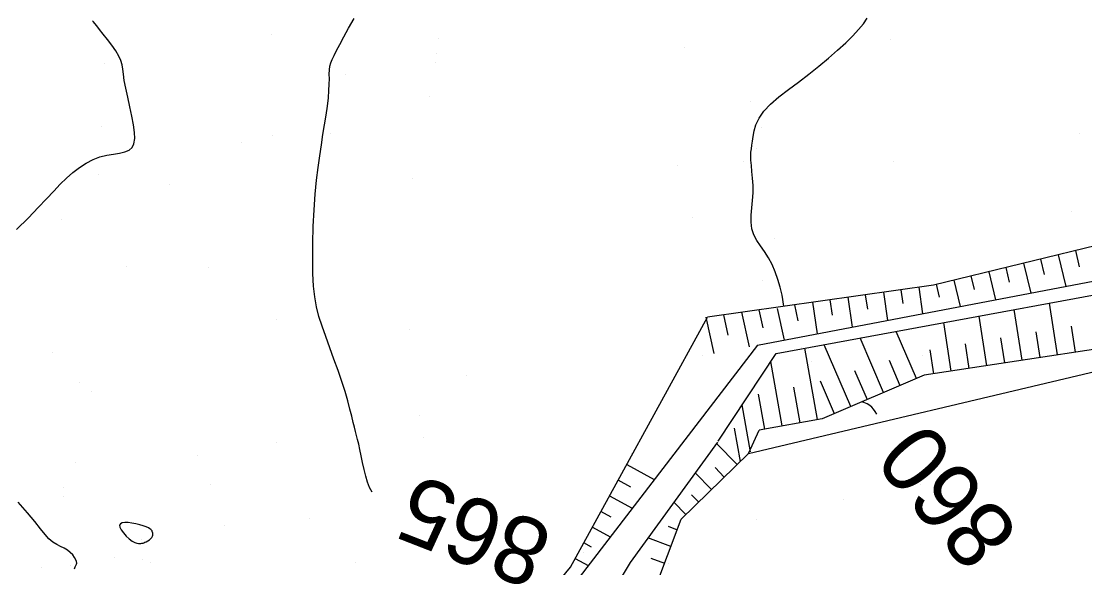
# Model space of a CAD drawing. Extents: x 400243 to 403697, y 4403637 to 4408083.
# Drawn here: x 402707.4 to 402826.2, y 4406153.3 to 4406214.4 of the extents above; entities that cross this region are included whole.
import ezdxf

# ---------------------------------------------------------------- set-up
doc = ezdxf.new("R2010")
doc.units = 0
doc.layers.add('HH_IC', color=7, linetype='Continuous')

msp = doc.modelspace()

# ---------------------------------------------------------------- linework, layer by layer
at = {"layer": 'HH_IC'}
for p, q in [((402735.33, 4406212.94), (402735.33, 4406212.94)), ((402753.96, 4406212.48), (402753.96, 4406212.48)), ((402781.49, 4406211.44), (402781.49, 4406211.44)), ((402804.51, 4406212.31), (402804.51, 4406212.31)), ((402753.8, 4406210.8), (402753.8, 4406210.8)), ((402716.69, 4406209.7), (402716.69, 4406209.7)), ((402753.64, 4406209.76), (402753.64, 4406209.76)), ((402743.57, 4406208.48), (402743.57, 4406208.48)), ((402752.98, 4406205.95), (402752.98, 4406205.95)), ((402788.87, 4406205.46), (402788.87, 4406205.46)), ((402716.39, 4406202.6), (402716.39, 4406202.6)), ((402741.88, 4406201.87), (402741.88, 4406201.87)), ((402790.13, 4406202.49), (402790.13, 4406202.49)), ((402825.61, 4406201.81), (402825.61, 4406201.81)), ((402732.02, 4406200.87), (402732.02, 4406200.87)), ((402735.48, 4406201.64), (402735.48, 4406201.64)), ((402789.54, 4406200.15), (402789.54, 4406200.15)), ((402780.67, 4406198.23), (402780.67, 4406198.23)), ((402788.06, 4406198.68), (402788.06, 4406198.68)), ((402804.78, 4406198.74), (402804.78, 4406198.74)), ((402715.98, 4406197.22), (402715.98, 4406197.22)), ((402723.95, 4406196.14), (402723.95, 4406196.14)), ((402751.05, 4406196.84), (402751.05, 4406196.84)), ((402850.92, 4406195), (402809.29, 4406184.89)), ((402711.84, 4406192.21), (402711.84, 4406192.21)), ((402782.4, 4406192.47), (402782.4, 4406192.47)), ((402824.71, 4406193.08), (402824.71, 4406193.08)), ((402789.65, 4406178.16), (402852.37, 4406190.15)), ((402791.52, 4406190.07), (402791.52, 4406190.07)), ((402825.63, 4406186.94), (402825.19, 4406188.75)), ((402791.71, 4406177.24), (402852.3, 4406188.43)), ((402821.72, 4406186.09), (402821.3, 4406187.81)), ((402823.24, 4406188.28), (402824.1, 4406184.75)), ((402719.14, 4406187.02), (402719.14, 4406187.02)), ((402728.28, 4406186.84), (402728.28, 4406186.84)), ((402815.47, 4406186.39), (402816.23, 4406183.24)), ((402817.81, 4406185.24), (402817.41, 4406186.86)), ((402819.35, 4406187.34), (402820.17, 4406184)), ((402790.23, 4406185.46), (402790.23, 4406185.46)), ((402811.58, 4406185.45), (402812.3, 4406182.49)), ((402813.89, 4406184.39), (402813.52, 4406185.92)), ((402809.29, 4406184.89), (402784.06, 4406181.32)), ((402803.7, 4406184.1), (402804.15, 4406180.94)), ((402805.9, 4406182.85), (402805.68, 4406184.38)), ((402807.66, 4406184.66), (402808.09, 4406181.69)), ((402809.29, 4406184.89), (402809.29, 4406184.89)), ((402809.98, 4406183.55), (402809.64, 4406184.98)), ((402794.2, 4406180.9), (402793.8, 4406182.69)), ((402793.91, 4406182.71), (402793.91, 4406182.71)), ((402795.78, 4406182.98), (402796.29, 4406179.43)), ((402798.01, 4406181.53), (402797.76, 4406183.26)), ((402799.74, 4406183.54), (402800.22, 4406180.18)), ((402801.95, 4406182.19), (402801.72, 4406183.82)), ((402823.15, 4406177.09), (402822.27, 4406182.88)), ((402786.36, 4406179.29), (402785.86, 4406181.57)), ((402787.84, 4406181.85), (402788.69, 4406177.98)), ((402790.28, 4406180.1), (402789.83, 4406182.13)), ((402791.85, 4406182.26), (402792.62, 4406178.73)), ((402819.2, 4406176.49), (402818.33, 4406182.16)), ((402735.85, 4406181.09), (402735.85, 4406181.09)), ((402768.75, 4406153.35), (402784.06, 4406181.32)), ((402783.87, 4406181.29), (402784.76, 4406177.23)), ((402788.65, 4406166.07), (402853.59, 4406181.46)), ((402811.29, 4406175.28), (402810.46, 4406180.7)), ((402815.25, 4406175.88), (402814.4, 4406181.43)), ((402824.68, 4406180.32), (402825.13, 4406177.4)), ((402750.77, 4406179.98), (402750.77, 4406179.98)), ((402807.4, 4406174.45), (402805.15, 4406179.72)), ((402820.74, 4406179.66), (402821.18, 4406176.79)), ((402789.65, 4406178.16), (402761.87, 4406142.01)), ((402794.54, 4406177.97), (402794.54, 4406177.97)), ((402800.05, 4406171.31), (402797.08, 4406178.23)), ((402803.72, 4406172.88), (402801.12, 4406178.98)), ((402829.98, 4406178.14), (402808.25, 4406174.81)), ((402829.98, 4406178.14), (402808.25, 4406174.81)), ((402812.85, 4406178.32), (402813.27, 4406175.58)), ((402816.79, 4406178.99), (402817.22, 4406176.19)), ((402710.9, 4406177.31), (402710.9, 4406177.31)), ((402783.46, 4406176.98), (402783.46, 4406176.98)), ((402785.23, 4406167.46), (402791.71, 4406177.24)), ((402791.71, 4406177.24), (402791.71, 4406177.24)), ((402796.33, 4406169.85), (402794.91, 4406177.83)), ((402808.12, 4406176.98), (402808.12, 4406176.98)), ((402808.91, 4406177.66), (402809.32, 4406174.98)), ((402792.4, 4406169.14), (402791.11, 4406176.34)), ((402795.7, 4406176.3), (402795.7, 4406176.3)), ((402804.35, 4406176.51), (402805.56, 4406173.67)), ((402757.15, 4406174.8), (402757.15, 4406174.8)), ((402780.25, 4406174.35), (402780.25, 4406174.35)), ((402808.25, 4406174.81), (402796.85, 4406169.94)), ((402808.25, 4406174.81), (402796.85, 4406169.94)), ((402800.49, 4406175.35), (402801.88, 4406172.09)), ((402808.25, 4406174.81), (402808.25, 4406174.81)), ((402713.91, 4406173.99), (402713.91, 4406173.99)), ((402793.65, 4406173.48), (402794.37, 4406169.5)), ((402796.64, 4406174.19), (402798.21, 4406170.52)), ((402715.23, 4406172.95), (402715.23, 4406172.95)), ((402785.05, 4406172.19), (402785.05, 4406172.19)), ((402789.73, 4406172.68), (402790.43, 4406168.79)), ((402788.85, 4406166.26), (402787.91, 4406171.51)), ((402751.86, 4406170.36), (402751.86, 4406170.36)), ((402796.85, 4406169.94), (402789.83, 4406168.68)), ((402796.85, 4406169.94), (402789.83, 4406168.68)), ((402796.85, 4406169.94), (402796.85, 4406169.94)), ((402787.04, 4406168.91), (402787.71, 4406165.16)), ((402788.65, 4406166.07), (402789.83, 4406168.68)), ((402735.88, 4406167.29), (402735.88, 4406167.29)), ((402752.32, 4406167.9), (402752.32, 4406167.9)), ((402785.18, 4406167.34), (402775.4, 4406153.87)), ((402785.23, 4406167.46), (402785.23, 4406167.46)), ((402781.12, 4406158.73), (402788.65, 4406166.07)), ((402781.15, 4406167.1), (402781.15, 4406167.1)), ((402787.37, 4406164.82), (402785.07, 4406167.18)), ((402788.65, 4406166.07), (402788.65, 4406166.07)), ((402713.47, 4406165.11), (402713.47, 4406165.11)), ((402727.05, 4406165.88), (402727.05, 4406165.88)), ((402775.52, 4406166.02), (402775.52, 4406166.02)), ((402775.04, 4406164.83), (402778.11, 4406163.15)), ((402784.5, 4406162.03), (402782.68, 4406163.9)), ((402784.9, 4406164.48), (402785.93, 4406163.43)), ((402728.49, 4406162.58), (402728.49, 4406162.58)), ((402775.48, 4406162.31), (402774.08, 4406163.08)), ((402807.89, 4406162.55), (402807.89, 4406162.55)), ((402712.07, 4406161.3), (402712.07, 4406161.3)), ((402712.12, 4406162.27), (402712.12, 4406162.27)), ((402754.69, 4406162.41), (402754.69, 4406162.41)), ((402773.11, 4406161.32), (402775.65, 4406159.94)), ((402782.28, 4406161.45), (402783.07, 4406160.63)), ((402781.64, 4406159.24), (402780.3, 4406160.61)), ((402799.24, 4406160.87), (402799.24, 4406160.87)), ((402773.28, 4406158.95), (402772.15, 4406159.57)), ((402730.08, 4406157.98), (402730.08, 4406157.98)), ((402739.62, 4406158.82), (402739.62, 4406158.82)), ((402760.84, 4406158.02), (402760.84, 4406158.02)), ((402771.19, 4406157.81), (402773.18, 4406156.73)), ((402775.64, 4406144.18), (402781.12, 4406158.73)), ((402779.65, 4406157.92), (402780.67, 4406157.54)), ((402781.12, 4406158.73), (402781.12, 4406158.73)), ((402789.57, 4406158.66), (402789.57, 4406158.66)), ((402779.96, 4406155.67), (402777.4, 4406156.63)), ((402720.84, 4406156.43), (402720.84, 4406156.43)), ((402752.94, 4406156), (402752.94, 4406156)), ((402771.09, 4406155.59), (402770.23, 4406156.06)), ((402717.84, 4406154.39), (402717.84, 4406154.39)), ((402720.93, 4406154.24), (402720.93, 4406154.24)), ((402769.27, 4406154.31), (402770.71, 4406153.52)), ((402770.25, 4406155.04), (402770.25, 4406155.04)), ((402777.72, 4406154.37), (402779.26, 4406153.8)), ((402709.61, 4406153.32), (402709.61, 4406153.32)), ((402712.93, 4406153.58), (402712.93, 4406153.58)), ((402721.85, 4406153.9), (402721.85, 4406153.9)), ((402744.67, 4406153.9), (402744.67, 4406153.9)), ((402775.4, 4406153.87), (402757.34, 4406124.13)), ((402757.7, 4406140), (402768.75, 4406153.35)), ((402768.75, 4406153.35), (402768.75, 4406153.35)), ((402779.68, 4406153.77), (402779.68, 4406153.77))]:
    msp.add_line(p, q, dxfattribs=at)
for points in [[(402706.85, 4406191.13), (402708.17, 4406192.43), (402709.27, 4406193.57), (402710.2, 4406194.55), (402711, 4406195.41), (402711.72, 4406196.17), (402712.42, 4406196.85), (402713.14, 4406197.48), (402713.87, 4406198.04), (402714.63, 4406198.53), (402715.4, 4406198.94), (402716.17, 4406199.23), (402716.94, 4406199.43), (402717.68, 4406199.55), (402718.36, 4406199.65), (402718.95, 4406199.78), (402719.43, 4406199.97), (402719.76, 4406200.28), (402719.96, 4406200.71), (402720.05, 4406201.27), (402720.03, 4406201.96), (402719.92, 4406202.8), (402719.74, 4406203.78), (402719.52, 4406204.84), (402719.28, 4406205.9), (402719.06, 4406206.91), (402718.89, 4406207.79), (402718.79, 4406208.49), (402718.72, 4406209.05), (402718.65, 4406209.54), (402718.52, 4406210), (402718.29, 4406210.5), (402717.94, 4406211.09), (402717.49, 4406211.73), (402717.01, 4406212.37), (402716.53, 4406212.97), (402716.12, 4406213.48), (402715.81, 4406213.87), (402715.59, 4406214.15), (402715.44, 4406214.33), (402715.35, 4406214.45)], [(402746.57, 4406161.72), (402746.28, 4406162.25), (402746.06, 4406162.86), (402745.87, 4406163.54), (402745.69, 4406164.27), (402745.52, 4406165.04), (402745.37, 4406165.79), (402745.22, 4406166.5), (402745.08, 4406167.12), (402744.96, 4406167.64), (402744.85, 4406168.09), (402744.73, 4406168.52), (402744.61, 4406168.99), (402744.46, 4406169.54), (402744.3, 4406170.22), (402744.09, 4406171.03), (402743.85, 4406171.96), (402743.55, 4406173), (402743.2, 4406174.13), (402742.78, 4406175.35), (402742.31, 4406176.61), (402741.84, 4406177.88), (402741.39, 4406179.13), (402740.98, 4406180.31), (402740.64, 4406181.4), (402740.38, 4406182.47), (402740.18, 4406183.57), (402740.04, 4406184.79), (402739.96, 4406186.18), (402739.94, 4406187.8), (402739.95, 4406189.59), (402740.01, 4406191.45), (402740.11, 4406193.3), (402740.23, 4406195.05), (402740.38, 4406196.63), (402740.54, 4406198.06), (402740.72, 4406199.36), (402740.91, 4406200.57), (402741.09, 4406201.72), (402741.27, 4406202.83), (402741.43, 4406203.9), (402741.58, 4406204.9), (402741.69, 4406205.82), (402741.76, 4406206.64), (402741.79, 4406207.36), (402741.8, 4406207.97), (402741.79, 4406208.5), (402741.81, 4406208.97), (402741.85, 4406209.38), (402741.95, 4406209.75), (402742.1, 4406210.14), (402742.32, 4406210.57), (402742.61, 4406211.11), (402742.98, 4406211.79), (402743.42, 4406212.64), (402743.95, 4406213.63), (402744.59, 4406214.71)], [(402792.57, 4406182.52), (402792.38, 4406183.78), (402792.18, 4406184.65), (402791.92, 4406185.52), (402791.61, 4406186.37), (402791.26, 4406187.19), (402790.86, 4406187.95), (402790.42, 4406188.64), (402789.98, 4406189.28), (402789.58, 4406189.89), (402789.24, 4406190.52), (402789.02, 4406191.19), (402788.92, 4406191.92), (402788.93, 4406192.7), (402789, 4406193.52), (402789.08, 4406194.37), (402789.14, 4406195.22), (402789.14, 4406196.05), (402789.09, 4406196.85), (402789.02, 4406197.6), (402788.95, 4406198.28), (402788.9, 4406198.86), (402788.88, 4406199.34), (402788.9, 4406199.75), (402788.95, 4406200.14), (402789.01, 4406200.53), (402789.08, 4406200.99), (402789.15, 4406201.53), (402789.26, 4406202.15), (402789.47, 4406202.83), (402789.81, 4406203.57), (402790.35, 4406204.34), (402791.1, 4406205.13), (402792.03, 4406205.93), (402793.09, 4406206.76), (402794.22, 4406207.6), (402795.38, 4406208.48), (402796.51, 4406209.37), (402797.59, 4406210.27), (402798.59, 4406211.15), (402799.5, 4406211.99), (402800.29, 4406212.76), (402800.94, 4406213.46), (402801.48, 4406214.1), (402801.91, 4406214.74)], [(402802.96, 4406170.46), (402802.77, 4406170.75), (402802.59, 4406171.01), (402802.41, 4406171.24), (402802.19, 4406171.44), (402801.91, 4406171.62), (402801.51, 4406171.78), (402801.28, 4406171.84)], [(402713.32, 4406153.18), (402713.39, 4406153.39), (402713.47, 4406153.54), (402713.54, 4406153.67), (402713.58, 4406153.81), (402713.56, 4406153.97), (402713.48, 4406154.19), (402713.33, 4406154.45), (402713.12, 4406154.73), (402712.85, 4406155), (402712.53, 4406155.25), (402712.17, 4406155.46), (402711.77, 4406155.66), (402711.35, 4406155.88), (402710.91, 4406156.16), (402710.47, 4406156.52), (402710.03, 4406157.01), (402709.52, 4406157.65), (402708.9, 4406158.45), (402708.09, 4406159.44), (402707.04, 4406160.63)], [(402721.35, 4406157.86), (402721.01, 4406157.98), (402720.61, 4406158.09), (402720.17, 4406158.2), (402719.73, 4406158.28), (402719.31, 4406158.33), (402718.94, 4406158.34), (402718.65, 4406158.3), (402718.45, 4406158.2), (402718.35, 4406158.04), (402718.38, 4406157.81), (402718.54, 4406157.51), (402718.79, 4406157.18), (402719.11, 4406156.83), (402719.45, 4406156.52), (402719.78, 4406156.27), (402720.06, 4406156.11), (402720.29, 4406156.02), (402720.48, 4406155.99), (402720.63, 4406155.99), (402720.74, 4406156.01), (402720.83, 4406156.02), (402720.91, 4406156.03), (402720.98, 4406156.05), (402721.07, 4406156.08), (402721.19, 4406156.13), (402721.34, 4406156.2), (402721.51, 4406156.3), (402721.69, 4406156.41), (402721.85, 4406156.54), (402721.98, 4406156.67), (402722.05, 4406156.81), (402722.08, 4406156.94), (402722.08, 4406157.06), (402722.06, 4406157.17), (402722.04, 4406157.25), (402722.02, 4406157.31), (402722.01, 4406157.35), (402722, 4406157.38), (402721.99, 4406157.41), (402721.96, 4406157.44), (402721.93, 4406157.5), (402721.87, 4406157.57), (402721.76, 4406157.65), (402721.59, 4406157.75), (402721.35, 4406157.86)]]:
    msp.add_lwpolyline(points, dxfattribs=at)

# ---------------------------------------------------------------- texts
for s, rotation, p in [('860', 130.3383, (402819.1, 4406157.26)), ('865', 158.7086, (402767.09, 4406157.75))]:
    msp.add_text(s, height=7.5, rotation=rotation, dxfattribs=at).set_placement(p)

doc.saveas('drawing.dxf')
